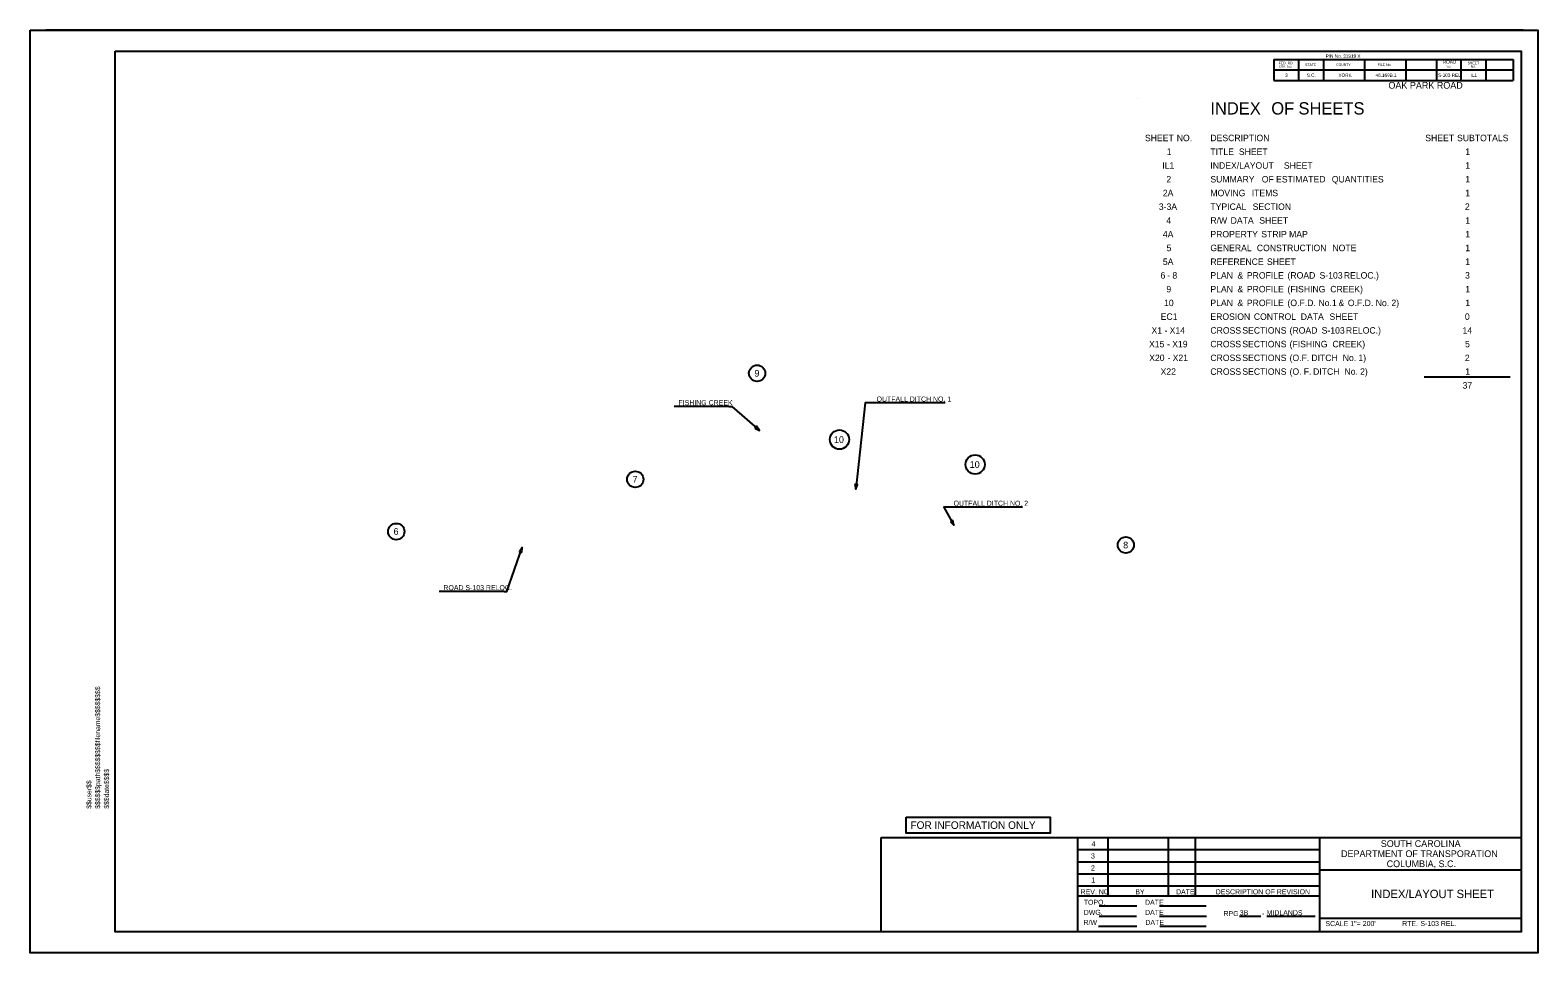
# Model space of a CAD drawing. Extents: x -796 to 2793, y -4650 to 4425.
# Drawn here: x 981 to 2777, y -125 to 975 of the extents above; entities that cross this region are included whole.
import ezdxf

# ---------------------------------------------------------------- set-up
doc = ezdxf.new("R2010")
doc.units = 0
for name, color, linetype in [('RD_HC_CL', 7, 'Continuous'), ('RD_HC_Data', 7, 'Continuous'), ('RD_HC_Data_Tic', 7, 'Continuous'), ('RD_SHT_Bndy', 7, 'Continuous'), ('RD_TX_Misc1', 7, 'Continuous')]:
    doc.layers.add(name, color=color, linetype=linetype)

msp = doc.modelspace()

# ---------------------------------------------------------------- linework, layer by layer
at = {"layer": 'RD_HC_CL'}
msp.add_lwpolyline([(981.4, 975), (2777.4, 975), (2777.4, -125), (981.4, -125)], close=True, dxfattribs=at)
at = {"layer": 'RD_HC_Data'}
for p, q in [((2760, 975), (1000, 975)), ((1000, 975), (2760, 975)), ((2463.1, 940), (2463.1, 915)), ((2463.1, 940), (2748.1, 940)), ((2492.1, 940), (2492.1, 915)), ((2522.1, 940), (2522.1, 915)), ((2571.1, 940), (2571.1, 915)), ((2620.1, 940), (2620.1, 915)), ((2656.6, 940), (2656.6, 915)), ((2685.6, 940), (2685.6, 915)), ((2715.6, 940), (2715.6, 915)), ((2748.1, 940), (2748.1, 915)), ((2463.1, 927.5), (2748.1, 927.5)), ((2463.1, 915), (2748.1, 915)), ((1995, 12.5), (2757.6, 12.5)), ((1995, -100), (1995, 12.5)), ((2229.6, -100), (2229.6, 12.5)), ((2229.6, 12.5), (2229.6, 12.5)), ((2265.6, -57.2), (2265.6, 12.5)), ((2337.6, -57.2), (2337.6, 12.5)), ((2369.4, -57.1), (2369.4, 12.5)), ((2517.6, -100), (2517.6, 12.5)), ((2229.6, -1.9), (2517.6, -1.9)), ((2229.6, -16.3), (2517.6, -16.3)), ((2229.6, -30.7), (2517.6, -30.7)), ((2517.6, -25.9), (2757.6, -25.9)), ((2229.6, -45.1), (2517.6, -45.1)), ((2229.6, -57.1), (2517.6, -57.1)), ((2255, -69.1), (2299.9, -69.1)), ((2326.8, -69.1), (2382.1, -69.1)), ((2255, -81.1), (2299.5, -81.1)), ((2326.8, -81.1), (2382.5, -81.1)), ((2422.1, -81.1), (2447.3, -81.1)), ((2454.5, -81.1), (2512, -81.1)), ((2517.6, -83.5), (2757.6, -83.5)), ((2254.2, -93.1), (2299.9, -93.1)), ((2327.2, -93.1), (2382.1, -93.1)), ((2760, -125), (1000, -125)), ((2760, -125), (1000, -125))]:
    msp.add_line(p, q, dxfattribs=at)
msp.add_lwpolyline([(1082.6, 950), (2757.6, 950), (2757.6, -100), (1082.6, -100)], close=True, dxfattribs=at)
at = {"layer": 'RD_HC_Data_Tic'}
msp.add_lwpolyline([(2025, 36.8), (2196.5, 36.8), (2196.5, 17.8), (2025, 17.8)], close=True, dxfattribs=at)
for centre, radius in [((1847.4, 565.9), 9.73), ((1945.5, 486.9), 11.5), ((2107.1, 457.2), 11.5), ((1702.2, 439.5), 9.72), ((1417.5, 377.3), 9.73), ((2286.6, 361.2), 9.67)]:
    msp.add_circle(centre, radius, dxfattribs=at)
at = {"layer": 'RD_SHT_Bndy'}
for p, q in [((2300, 893.5), (2300, 893.5)), ((2641.9, 561.8), (2744.3, 561.8)), ((1813.6, 526.4), (1748.7, 526.4)), ((2071.4, 530.7), (1984.7, 530.7)), ((2163.7, 406.5), (2076.4, 406.5)), ((1546.1, 305.9), (1468.7, 305.9))]:
    msp.add_line(p, q, dxfattribs=at)
for points in [[(1813.6, 526.4), (1817.1, 526.4), (1850.2, 497.8)], [(1984.7, 530.7), (1975.9, 530.7), (1964.9, 427.8)], [(2076.4, 406.5), (2069.8, 406.5), (2081.9, 384.7)], [(1546.1, 305.9), (1549.3, 305.9), (1567.6, 358.1)]]:
    msp.add_lwpolyline(points, dxfattribs=at)
for points in [[(1844.8, 500.4), (1850.2, 497.8), (1846.8, 502.7)], [(1963.9, 433.8), (1964.9, 427.8), (1967, 433.4)], [(2077.7, 389), (2081.9, 384.7), (2080.4, 390.5)], [(1567.2, 352.1), (1567.6, 358.1), (1564.2, 353.1)]]:
    msp.add_lwpolyline(points, close=True, dxfattribs=at)

# ---------------------------------------------------------------- texts
at = {"layer": 'RD_HC_Data_Tic'}
for s, height, p in [('FED. RD.', 3, (2468.7, 934.3)), ('STATE', 3, (2500.1, 932.3)), ('PIN No. 31919 X   ', 4, (2524.7, 942)), ('COUNTY', 3, (2537.1, 932.3)), ('FILE No.', 3, (2586.6, 932.3)), ('      ROAD      ', 4, (2655, 935.1)), ('SHEET', 3, (2693.7, 934.3)), ('DIV. No.', 3, (2469.3, 930.2)), ('3', 4, (2476.4, 919.3)), ('S.C.', 4, (2502.1, 919.3)), ('      YORK      ', 4, (2530.7, 919.3)), ('   46.169B.1    ', 4, (2579.4, 919.3)), ('   S-103 REL.   ', 4, (2653.9, 919.3)), ('No.', 3, (2667.9, 930.2)), ('      IL1       ', 4, (2688, 919.3)), ('No.', 3, (2697.4, 930.2)), ('OAK PARK ROAD                 ', 8, (2599.4, 905.2)), ('FOR INFORMATION ONLY', 9, (2030, 22.8)), ('4', 6.24, (2245.8, 1.9)), ('SOUTH CAROLINA', 8, (2590.3, 1.2)), ('3', 6.24, (2245, -12.5)), ('DEPARTMENT OF TRANSPORATION', 8, (2543, -10.8)), ('COLUMBIA, S.C.', 8, (2597.3, -22.8)), ('2', 6.24, (2245, -26.9)), ('1', 6.24, (2245.4, -41.3)), ('REV. NO.', 6, (2232.7, -55.2)), ('BY', 6, (2297.9, -55.2)), ('DATE', 6, (2346.4, -55.2)), ('DESCRIPTION OF REVISION', 6, (2393.7, -55.2)), ('      INDEX/LAYOUT SHEET       ', 10, (2556.5, -59.7)), ('TOPO.', 6, (2236.5, -67.7)), ('DATE', 6, (2309.5, -67.7)), ('R/W', 6, (2236.2, -91.7)), ('DWG.', 6, (2236.5, -79.7)), ('DATE', 6, (2309.5, -79.7)), ('DATE', 6, (2309.9, -91.7)), ('RPG', 6, (2403, -81.1)), ('3B    ', 6, (2422.3, -80.1)), ('-', 6, (2448.7, -81.1)), ('MIDLANDS   ', 6, (2454.3, -80.1)), ('SCALE 1"=', 6, (2524.4, -93.1)), ("200'       ", 6, (2568.8, -93)), ('RTE.', 6, (2615.8, -93.1)), ('S-103 REL. ', 6, (2637.5, -93))]:
    msp.add_text(s, height=height, dxfattribs=at).set_placement(p)
at = {"layer": 'RD_SHT_Bndy'}
for s, height, p in [('INDEX', 14.7, (2387.3, 874.4)), (' OF', 14.7, (2454.4, 874.4)), (' SHEETS', 14.7, (2486.8, 874.4)), ('SHEET', 7.7, (2309.4, 842.6)), (' NO.', 7.7, (2344.4, 842.6)), ('DESCRIPTION', 7.7, (2387.3, 842.6)), ('SHEET', 7.7, (2643.3, 842.6)), (' SUBTOTALS', 7.7, (2678.3, 842.6)), ('1', 7.7, (2335.3, 826.2)), ('TITLE', 7.7, (2387.3, 826.2)), (' SHEET', 7.7, (2418.4, 826.2)), ('1', 7.7, (2690.9, 826.2)), ('IL1', 7.7, (2330, 809.8)), ('INDEX/LAYOUT', 7.7, (2387.3, 809.8)), (' SHEET', 7.7, (2472, 809.8)), ('1', 7.7, (2690.9, 809.8)), ('2', 7.7, (2334.9, 793.4)), ('SUMMARY', 7.7, (2387.3, 793.4)), (' OF', 7.7, (2445.7, 793.4)), (' ESTIMATED', 7.7, (2462.7, 793.4)), (' QUANTITIES', 7.7, (2529.1, 793.4)), ('1', 7.7, (2690.9, 793.4)), ('2A', 7.7, (2330.7, 777)), ('MOVING', 7.7, (2387.3, 777)), (' ITEMS', 7.7, (2433.7, 777)), ('1', 7.7, (2690.9, 777)), ('3-3A', 7.7, (2325.9, 760.7)), ('TYPICAL', 7.7, (2387.3, 760.7)), (' SECTION', 7.7, (2434.8, 760.7)), ('2', 7.7, (2690.5, 760.7)), ('4', 7.7, (2334.9, 744.3)), ('R/W', 7.7, (2387.3, 744.3)), (' DATA', 7.7, (2408.6, 744.3)), (' SHEET', 7.7, (2442.7, 744.3)), ('1', 7.7, (2690.9, 744.3)), ('4A', 7.7, (2330.7, 727.9)), ('5', 7.7, (2335.1, 711.5)), ('GENERAL', 7.7, (2387.3, 711.5)), ('PROPERTY', 7.7, (2387.3, 727.9)), (' CONSTRUCTION', 7.7, (2439.8, 711.5)), (' STRIP', 7.7, (2445.1, 727.9)), (' MAP', 7.7, (2478.2, 727.9)), (' NOTE', 7.7, (2529.8, 711.5)), ('1', 7.7, (2690.9, 727.9)), ('1', 7.7, (2690.9, 711.5)), ('5A', 7.7, (2330.7, 695.1)), ('REFERENCE', 7.7, (2387.3, 695.1)), (' SHEET', 7.7, (2451.8, 695.1)), ('1', 7.7, (2690.9, 695.1)), ('6', 7.7, (2327.9, 678.8)), (' 8', 7.7, (2339.2, 678.8)), ('PLAN', 7.7, (2387.3, 678.8)), (' &', 7.7, (2416.7, 678.8)), (' PROFILE', 7.7, (2427.9, 678.8)), (' (ROAD', 7.7, (2476.3, 678.8)), (' S-103', 7.7, (2514.5, 678.8)), (' RELOC.)', 7.7, (2543.4, 678.8)), ('3', 7.7, (2690.7, 678.8)), ('9', 7.7, (2334.9, 662.4)), (' -', 7.7, (2333.1, 678.8)), ('PLAN', 7.7, (2387.3, 662.4)), (' &', 7.7, (2416.7, 662.4)), (' PROFILE', 7.7, (2427.9, 662.4)), (' (FISHING', 7.7, (2476.3, 662.4)), (' CREEK)', 7.7, (2527.3, 662.4)), ('1', 7.7, (2690.9, 662.4)), ('10', 7.7, (2332.1, 646)), ('PLAN', 7.7, (2387.3, 646)), (' &', 7.7, (2416.7, 646)), (' PROFILE', 7.7, (2427.9, 646)), (' (O.F.D.', 7.7, (2476.3, 646)), (' No.1', 7.7, (2513.2, 646)), (' &', 7.7, (2537.1, 646)), (' O.F.D.', 7.7, (2548.2, 646)), (' No.', 7.7, (2581.4, 646)), (' 2)', 7.7, (2600.1, 646)), ('1', 7.7, (2690.9, 646)), ('EC1', 7.7, (2328.1, 629.6)), ('EROSION', 7.7, (2387.3, 629.6)), (' CONTROL', 7.7, (2436.2, 629.6)), (' DATA', 7.7, (2492.1, 629.6)), (' SHEET', 7.7, (2526.3, 629.6)), ('0', 7.7, (2690.5, 629.6)), ('X1', 7.7, (2317.2, 613.2)), (' -', 7.7, (2329.8, 613.2)), (' X14', 7.7, (2335.9, 613.2)), ('CROSS', 7.7, (2387.3, 613.2)), (' SECTIONS', 7.7, (2422.5, 613.2)), (' (ROAD', 7.7, (2478.8, 613.2)), (' S-103', 7.7, (2517, 613.2)), (' RELOC.)', 7.7, (2545.9, 613.2)), ('14', 7.7, (2687.7, 613.2)), ('X15', 7.7, (2314.2, 596.9)), (' -', 7.7, (2332.9, 596.9)), (' X19', 7.7, (2339, 596.9)), ('CROSS', 7.7, (2387.3, 596.9)), (' SECTIONS', 7.7, (2422.5, 596.9)), (' (FISHING', 7.7, (2478.8, 596.9)), (' CREEK)', 7.7, (2529.9, 596.9)), ('5', 7.7, (2690.7, 596.9)), ('X20', 7.7, (2314.4, 580.5)), (' -', 7.7, (2333.4, 580.5)), (' X21', 7.7, (2339.5, 580.5)), ('CROSS', 7.7, (2387.3, 580.5)), (' SECTIONS', 7.7, (2422.5, 580.5)), (' (O.F.', 7.7, (2478.8, 580.5)), (' DITCH', 7.7, (2504.7, 580.5)), (' No.', 7.7, (2542.1, 580.5)), (' 1)', 7.7, (2560.8, 580.5)), ('2', 7.7, (2690.5, 580.5)), ('9', 8, (1844.2, 561.9)), ('X22', 7.7, (2328, 564.1)), ('CROSS', 7.7, (2387.3, 564.1)), (' SECTIONS', 7.7, (2422.5, 564.1)), (' (O.', 7.7, (2478.8, 564.1)), (' F.', 7.7, (2495.6, 564.1)), (' DITCH', 7.7, (2506.8, 564.1)), (' No.', 7.7, (2544.2, 564.1)), (' 2)', 7.7, (2562.8, 564.1)), ('1', 7.7, (2690.9, 564.1)), ('37', 7.7, (2687.7, 547.7)), ('FISHING CREEK', 6, (1753.7, 527.9)), ('OUTFALL DITCH NO. 1', 6, (1989.7, 532.2)), ('10', 8, (1938.9, 482.9)), ('10', 8, (2100.6, 453.2)), ('7', 8, (1699, 435.5)), ('OUTFALL DITCH NO. 2', 6, (2081.4, 408)), ('6', 8, (1414.3, 373.3)), ('8', 8, (2283.4, 357.2)), ('ROAD S-103 RELOC.', 6, (1473.7, 307.4))]:
    msp.add_text(s, height=height, dxfattribs=at).set_placement(p)
at = {"layer": 'RD_TX_Misc1'}
for s, p in [('$$$$$$path$$$$$$$$filename$$$$$$$$', (1064.8, 46.8)), ('$$$date$$$$', (1075.3, 46.8)), ('$$user$$', (1054.3, 46.8))]:
    msp.add_text(s, height=5.88, rotation=90, dxfattribs=at).set_placement(p)

doc.saveas('drawing.dxf')
